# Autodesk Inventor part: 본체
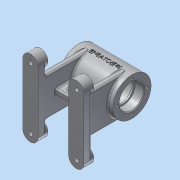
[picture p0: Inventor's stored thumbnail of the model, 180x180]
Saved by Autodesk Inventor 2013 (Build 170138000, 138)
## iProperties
Created: 2015-11
Part Number: 본체
Material: 알루미늄 6061
Document SubType Name: Modeling
Designer: Administrator
Density: 2.71 g/cm^3
Mass: 359.025 g
Surface Area: 459.453 cm^2
Volume: 132.482 cm^3
Author: Administrator
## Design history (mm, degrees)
sketch "스케치1"
  geometry: L1 (-35, 0)-(35, 0); L2 (-35, 16)-(-23, 16); L3 (-23, 16)-(-23, 14); L4 (-23, 14)-(-21, 14); L5 (-21, 14)-(-21, 21); L6 (-21, 21)-(21, 21); L7 (21, 21)-(21, 14); L8 (21, 14)-(23, 14); L9 (23, 14)-(23, 16); L10 (23, 16)-(35, 16); L11 (35, 16)-(35, 25); L12 (35, 25)-(-35, 25); L13 (-35, 25)-(-35, 16); 2 further points
  constraints: 26 end point, 7 parallel, 5 perpendicular, 2 coincident, 2 vertical alignment, 1 horizontal, 1 midpoint
  dimensions: "d0" = 70 distance of L1.start L1.end; "d1" = 42 diameter of L6 L1; "d2" = 32 diameter of L2 L1; "d3" = 28 diameter of L4 L1; "d4" = 28 diameter of L8 L1; "d5" = 32 diameter of L10 L1; "d6" = 50 diameter of L12 L1; "d7" = 12 distance between parallel lines of L3 L13; "d8" = 2 distance between parallel lines of L5 L3; "d9" = 42 distance between parallel lines of L7 L5; "d10" = 12 distance between parallel lines of L11 L9
revolve "회전1" sketch "스케치1" stored, may be unused: angle "d11" = 90 deg
sketch "스케치2"
  geometry: L1 (0, 0)-(-24.249, -14); L2 (0, 0)-(28, 0); C1 r 25 at (0, 0) reference; C2 r 21 at (0, 0) reference; 1 further point
  constraints: 4 end point, 1 equal length, 1 horizontal
  dimensions: "d12" = 28 distance of L1.start L1.end; "d13" = 150 deg angle of L1 L2
  node "절단 모서리 투영1"
node "작업 평면1"
sketch "스케치3"
  geometry: C1 r 6 at (0, 0); 1 further point
  constraints: 1 centre point, 1 coincident
  dimensions: "d14" = 12 diameter of C1
extrude "돌출1" join sketch "스케치3" stored distance "d15" = 10; taper "d16" = 0 deg
node "작업 평면2"
sketch "스케치4"
  geometry: L1 (20, -50)-(40, -50); L2 (40, -50)-(40, 50); L3 (40, 50)-(20, 50); L4 (20, 50)-(20, -50); L5 (-40, -50)-(-20, -50); L6 (-20, -50)-(-20, 50); L7 (-20, 50)-(-40, 50); L8 (-40, 50)-(-40, -50); 3 further points
  constraints: 16 end point, 4 parallel, 2 horizontal, 2 horizontal alignment, 2 midpoint, 2 perpendicular
  dimensions: "d18" = 100 distance of L1.end L2.end; "d20" = 100 distance of L7.end L5.start; "d21" = 20 distance of L6.end L7.end; "d22" = 20 distance between parallel lines of L2 L4; "d23" = 40 distance from line of L8 point (0, 0); "d24" = 80 distance between parallel lines of L2 L8
extrude "돌출2" join sketch "스케치4" distance "d25" = 10; taper "d26" = 0 deg
fillet "모깎기1" dims "d27" = 10
sketch "스케치5"
  geometry: L1 (20, 40)-(20, -40) reference; L2 (20, -25)-(28, -25); L3 (28, -25)-(28, 25); L4 (28, 25)-(20, 25); L5 (20, 25)-(20, -25); 2 further points
  constraints: 8 end point, 2 parallel, 1 collinear, 1 horizontal, 1 horizontal alignment, 1 midpoint, 1 perpendicular
  dimensions: "d28" = 50 distance between parallel lines of L4 L2; "d30" = 8 distance between parallel lines of L3 L5
extrude "돌출3" join sketch "스케치5" stored distance "d31" = 10; taper "d32" = 0 deg
node "작업 평면3"
sketch "스케치6"
  geometry: L1 (20, 25)-(28, 25) reference; L2 (28, 25)-(28, -25) reference; L3 (28, -25)-(20, -25) reference; L4 (20, -25)-(20, 25) reference; L5 (-28, 25)-(-20, 25) reference; L6 (-20, 25)-(-20, -25) reference; L7 (-20, -25)-(-28, -25) reference; L8 (-28, -25)-(-28, 25) reference; L9 (-20, 4)-(20, 4); L10 (20, 4)-(20, -4); L11 (20, -4)-(-20, -4); L12 (-20, -4)-(-20, 4); 2 further points
  constraints: 8 end point, 2 collinear, 2 parallel, 1 horizontal, 1 horizontal alignment, 1 midpoint, 1 perpendicular
  dimensions: "d34" = 8 distance between parallel lines of L11 L9
extrude "돌출4" join sketch "스케치6" stored distance "d36" = 10; taper "d37" = 0 deg
sketch "스케치7"
  geometry: L1 (0, -23)-(-20, -23) reference; L2 (12, 6.5)-(28, 6.5); L3 (28, 13.5)-(12, 13.5); A1 r 3.5 centre (12, 10) between (12, 13.5) and (12, 6.5); A2 r 3.5 centre (28, 10) between (28, 6.5) and (28, 13.5); 1 further point
  constraints: 4 end point, 4 point on circle, 3 tangent, 2 centre point, 1 horizontal alignment, 1 parallel
  dimensions: "d38" = 7 diameter of A1; "d39" = 7 diameter of A2; "d40" = 8 horizontal distance of A1.centre point (20, 45); "d41" = 23 dimension on A2 A1; "d42" = 33 distance from line of L1 A1.centre
extrude "돌출5" cut sketch "스케치7" stored distance "d43" = 10; taper "d44" = 0 deg
node "작업 평면4"
sketch "스케치8"
  geometry: C1 r 5 at (0, 0); 1 further point
  constraints: 1 centre point, 1 coincident
  dimensions: "d46" = 10 diameter of C1
extrude "돌출6" join sketch "스케치8" stored distance "d47" = 10; taper "d48" = 0 deg
sketch "스케치9"
  geometry: C1 r 10 at (-30, 40); C2 r 10 at (-30, -40); A1 r 10 centre (-30, 40) between (-20, 40) and (-40, 40) reference; A2 r 10 centre (-30, -40) between (-40, -40) and (-20, -40) reference; 1 further point
  constraints: 2 centre point, 2 coincident
  dimensions: "d49" = 20 diameter of C1; "d50" = 20 diameter of C2
extrude "돌출7" join sketch "스케치9" distance "d51" = 3; taper "d52" = 0 deg
hole "구멍1" diameter "d55" = 6; stored, may be unused: countersink angle "d59" = 90 deg, drill point angle "d61" = 0 deg; dims "d53" = 10, "d54" = 10, "d56" = 6, "d57" = 12, "d58" = 4, "d60" = 12
hole "구멍2" diameter "d64" = 5.188; stored, may be unused: countersink angle "d68" = 90 deg, drill point angle "d70" = 118 deg; dims "d62" = 10, "d63" = 10, "d65" = 6, "d66" = 1, "d67" = 4, "d69" = 12
hole "구멍3" diameter "d73" = 5.188; stored, may be unused: countersink angle "d77" = 90 deg, drill point angle "d79" = 118 deg; dims "d71" = 10, "d72" = 10, "d74" = 6, "d75" = 1, "d76" = 4, "d78" = 12
sketch "스케치10"
  geometry: C1 r 16 at (0, 0) reference; 1 further point
  constraints: 1 vertical alignment
  dimensions: "d80" = 20 distance of C1.centre point (0, 20)
hole "구멍4" sketch "스케치10" at (0, 20) diameter "d81" = 3.242; stored, may be unused: countersink angle "d85" = 90 deg, drill point angle "d87" = 118 deg; dims "d82" = 8, "d83" = 1, "d84" = 4, "d86" = 10
fillet "모깎기2" dims "d91" = 0.3
chamfer "모따기1" distance "d92" = 1; stored, may be unused: second distance "d93" = 2, angle "d94" = 45 deg
chamfer "모따기2" distance "d95" = 1; stored, may be unused: second distance "d96" = 2, angle "d97" = 45 deg
fillet "모깎기3" dims "d98" = 0.3
fillet "모깎기4" dims "d99" = 3
fillet "모깎기5" dims "d100" = 2
fillet "모깎기6" dims "d101" = 2
fillet "모깎기7" dims "d102" = 2
fillet "모깎기11" dims "d106" = 2
fillet "모깎기12" dims "d107" = 2
fillet "모깎기13" dims "d108" = 2
fillet "모깎기14" dims "d109" = 2
node "작업 평면5"
sketch "스케치11"
  geometry: L1 (-35, -25)-(-35, 25) reference; L2 (40, -58)-(40, -68) reference; L3 (40, -68)-(20, -68) reference; L4 (20, -68)-(20, -58) reference; L5 (22, -58)-(22, 0) reference; L6 (-22, 0)-(22, 0) reference; L7 (-22, -58)-(-22, 0) reference; L8 (-26, -58)-(-26, 0) reference; L9 (-35, 0)-(-26, 0) reference; L10 (26, -58)-(26, 0) reference; L11 (22, 0)-(26, 0) reference; L12 (-26, 0)-(-22, 0) reference; L13 (-20, -58)-(-20, -68) reference; L14 (-20, -68)-(-40, -68) reference; L15 (-40, -68)-(-40, -58) reference; L16 (26, 0)-(35, 0) reference; L17 (20, -58)-(22, -58) reference; L18 (26, -58)-(40, -58) reference; L19 (22, -58)-(26, -58) reference; L20 (-40, -58)-(-26, -58) reference; L21 (-22, -58)-(-20, -58) reference; L22 (-26, -58)-(-22, -58) reference; 2 further points
  constraints: 1 other
  dimensions: "d110" = 35 distance from line of point (0, 0) L1; "d111" = 25 vertical distance of point (0, 0) L1.end
feature "엠보싱1" sketch "스케치11" dims "d12" = 28, "d13" = 150 deg, "d112" = 0.5, "d113" = 0
fillet "모깎기15" dims "d114" = 2
fillet "모깎기16" dims "d115" = 2
node "솔리드1"
mirror "대칭1"
mirror "대칭2"
mirror "대칭3"
pattern_circular "원형 패턴1" dims angle "d89" = 360 deg
mirror "대칭4"
node "절단 모서리 투영2"
node "절단 모서리 투영3"
other parameters: "d17" = -68, "d33" = -23, "d45" = 28
